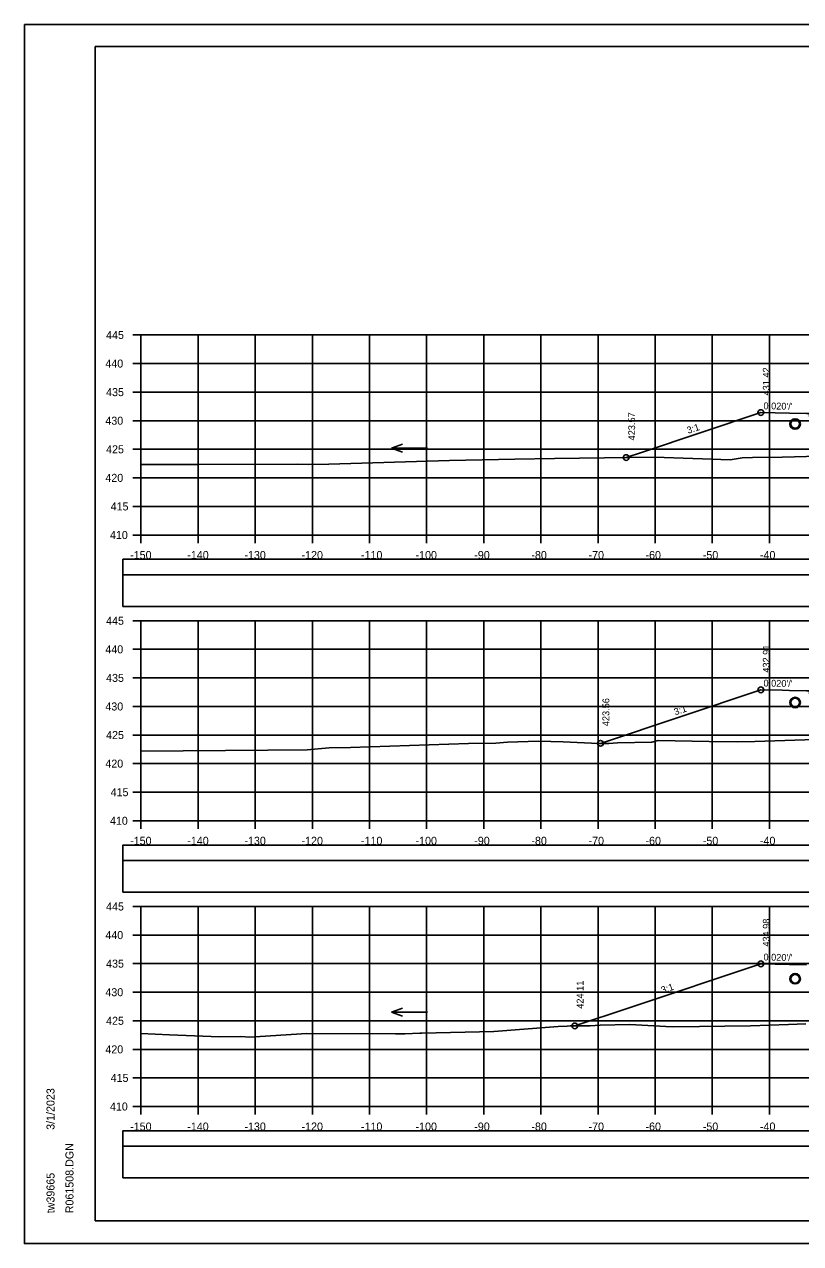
# Model space of a CAD drawing. Extents: x 1371057 to 1372761, y 380005 to 390517.
# Drawn here: x 1371390.5 to 1371526.3, y 384698.5 to 384911.8 of the extents above; entities that cross this region are included whole.
import ezdxf

# ---------------------------------------------------------------- set-up
doc = ezdxf.new("R2010")
doc.units = 0
for name, color, linetype in [('R_Axis', 7, 'Continuous'), ('R_Axis Annot', 7, 'Continuous'), ('R_Border', 7, 'Continuous'), ('R_Detour', 7, 'Continuous'), ('R_Dimension', 7, 'Continuous'), ('R_Exist Surface', 7, 'Continuous'), ('R_Fin Surface', 7, 'Continuous'), ('R_Grid', 7, 'Continuous'), ('R_No Plot', 7, 'Continuous'), ('R_Water', 7, 'Continuous'), ('R_Water Annot', 7, 'Continuous'), ('R_Xsect Elev', 7, 'Continuous'), ('R_Xsect Slope', 7, 'Continuous')]:
    doc.layers.add(name, color=color, linetype=linetype)

msp = doc.modelspace()

# ---------------------------------------------------------------- linework, layer by layer
at = {"layer": 'R_Axis'}
for p, q in [((1371409.47, 384857.5), (1371410.87, 384857.5)), ((1371410.87, 384822.5), (1371410.87, 384857.5)), ((1371409.47, 384852.5), (1371410.87, 384852.5)), ((1371409.47, 384847.5), (1371410.87, 384847.5)), ((1371409.47, 384842.5), (1371410.87, 384842.5)), ((1371409.47, 384837.5), (1371410.87, 384837.5)), ((1371409.47, 384832.5), (1371410.87, 384832.5)), ((1371409.47, 384827.5), (1371410.87, 384827.5)), ((1371409.47, 384822.5), (1371410.87, 384822.5)), ((1371410.87, 384822.5), (1371710.87, 384822.5)), ((1371410.87, 384821.1), (1371410.87, 384822.5)), ((1371420.87, 384821.1), (1371420.87, 384822.5)), ((1371430.87, 384821.1), (1371430.87, 384822.5)), ((1371440.87, 384821.1), (1371440.87, 384822.5)), ((1371450.87, 384821.1), (1371450.87, 384822.5)), ((1371460.87, 384821.1), (1371460.87, 384822.5)), ((1371470.87, 384821.1), (1371470.87, 384822.5)), ((1371480.87, 384821.1), (1371480.87, 384822.5)), ((1371490.87, 384821.1), (1371490.87, 384822.5)), ((1371500.87, 384821.1), (1371500.87, 384822.5)), ((1371510.87, 384821.1), (1371510.87, 384822.5)), ((1371520.87, 384821.1), (1371520.87, 384822.5)), ((1371409.47, 384807.5), (1371410.87, 384807.5)), ((1371410.87, 384772.5), (1371410.87, 384807.5)), ((1371409.47, 384802.5), (1371410.87, 384802.5)), ((1371409.47, 384797.5), (1371410.87, 384797.5)), ((1371409.47, 384792.5), (1371410.87, 384792.5)), ((1371409.47, 384787.5), (1371410.87, 384787.5)), ((1371409.47, 384782.5), (1371410.87, 384782.5)), ((1371409.47, 384777.5), (1371410.87, 384777.5)), ((1371409.47, 384772.5), (1371410.87, 384772.5)), ((1371410.87, 384772.5), (1371710.87, 384772.5)), ((1371410.87, 384771.1), (1371410.87, 384772.5)), ((1371420.87, 384771.1), (1371420.87, 384772.5)), ((1371430.87, 384771.1), (1371430.87, 384772.5)), ((1371440.87, 384771.1), (1371440.87, 384772.5)), ((1371450.87, 384771.1), (1371450.87, 384772.5)), ((1371460.87, 384771.1), (1371460.87, 384772.5)), ((1371470.87, 384771.1), (1371470.87, 384772.5)), ((1371480.87, 384771.1), (1371480.87, 384772.5)), ((1371490.87, 384771.1), (1371490.87, 384772.5)), ((1371500.87, 384771.1), (1371500.87, 384772.5)), ((1371510.87, 384771.1), (1371510.87, 384772.5)), ((1371520.87, 384771.1), (1371520.87, 384772.5)), ((1371409.47, 384757.5), (1371410.87, 384757.5)), ((1371410.87, 384722.5), (1371410.87, 384757.5)), ((1371409.47, 384752.5), (1371410.87, 384752.5)), ((1371409.47, 384747.5), (1371410.87, 384747.5)), ((1371409.47, 384742.5), (1371410.87, 384742.5)), ((1371409.47, 384737.5), (1371410.87, 384737.5)), ((1371409.47, 384732.5), (1371410.87, 384732.5)), ((1371409.47, 384727.5), (1371410.87, 384727.5)), ((1371409.47, 384722.5), (1371410.87, 384722.5)), ((1371410.87, 384722.5), (1371710.87, 384722.5)), ((1371410.87, 384721.1), (1371410.87, 384722.5)), ((1371420.87, 384721.1), (1371420.87, 384722.5)), ((1371430.87, 384721.1), (1371430.87, 384722.5)), ((1371440.87, 384721.1), (1371440.87, 384722.5)), ((1371450.87, 384721.1), (1371450.87, 384722.5)), ((1371460.87, 384721.1), (1371460.87, 384722.5)), ((1371470.87, 384721.1), (1371470.87, 384722.5)), ((1371480.87, 384721.1), (1371480.87, 384722.5)), ((1371490.87, 384721.1), (1371490.87, 384722.5)), ((1371500.87, 384721.1), (1371500.87, 384722.5)), ((1371510.87, 384721.1), (1371510.87, 384722.5)), ((1371520.87, 384721.1), (1371520.87, 384722.5))]:
    msp.add_line(p, q, dxfattribs=at)
at = {"layer": 'R_Border'}
for p, q in [((1371402.87, 384907.96), (1371719.05, 384907.96)), ((1371402.87, 384702.5), (1371402.87, 384907.96)), ((1371402.87, 384702.5), (1371402.87, 384702.5)), ((1371719.05, 384702.5), (1371402.87, 384702.5))]:
    msp.add_line(p, q, dxfattribs=at)
at = {"layer": 'R_Detour'}
for points in [[(1371407.72, 384815.54), (1371714.03, 384815.54), (1371714.03, 384818.25), (1371407.72, 384818.25)], [(1371407.72, 384765.54), (1371714.03, 384765.54), (1371714.03, 384768.25), (1371407.72, 384768.25)], [(1371407.72, 384715.54), (1371714.03, 384715.54), (1371714.03, 384718.25), (1371407.72, 384718.25)]]:
    msp.add_lwpolyline(points, close=True, dxfattribs=at)
at = {"layer": 'R_Dimension'}
for points in [[(1371407.72, 384810.02), (1371714.03, 384810.02), (1371714.03, 384815.54), (1371407.72, 384815.54)], [(1371407.72, 384760.02), (1371714.03, 384760.02), (1371714.03, 384765.54), (1371407.72, 384765.54)], [(1371407.72, 384710.02), (1371714.03, 384710.02), (1371714.03, 384715.54), (1371407.72, 384715.54)]]:
    msp.add_lwpolyline(points, close=True, dxfattribs=at)
at = {"layer": 'R_Exist Surface'}
for points in [[(1371410.87, 384834.84), (1371420.98, 384834.82), (1371438.32, 384834.89), (1371440.14, 384834.83), (1371443.77, 384834.92), (1371464.89, 384835.56), (1371476.28, 384835.8), (1371483.26, 384835.88), (1371500.77, 384836.13), (1371509.16, 384835.83), (1371513.98, 384835.65), (1371516.11, 384835.99), (1371517.93, 384836.08), (1371523.12, 384836.1), (1371529.53, 384836.32)], [(1371410.87, 384784.67), (1371433.09, 384784.85), (1371439.98, 384784.93), (1371443.84, 384785.25), (1371447.53, 384785.3), (1371468.18, 384786), (1371473.01, 384786.07), (1371475.04, 384786.24), (1371480.47, 384786.42), (1371484.74, 384786.29), (1371490.93, 384786.05), (1371492.79, 384786.05), (1371494.29, 384786.12), (1371500.3, 384786.23), (1371501.4, 384786.56), (1371510.32, 384786.36), (1371515.36, 384786.3), (1371518.3, 384786.39), (1371530.57, 384786.76)], [(1371410.87, 384735.27), (1371415.89, 384735.02), (1371424.63, 384734.72), (1371428.36, 384734.77), (1371429.95, 384734.65), (1371439.93, 384735.3), (1371455.4, 384735.21), (1371456.56, 384735.21), (1371457.05, 384735.24), (1371459.69, 384735.31), (1371460.02, 384735.34), (1371472.66, 384735.62), (1371483.89, 384736.48), (1371485.49, 384736.57), (1371486.02, 384736.6), (1371489.47, 384736.64), (1371491.26, 384736.71), (1371496.44, 384736.86), (1371502.75, 384736.51), (1371504.13, 384736.44), (1371517.56, 384736.62), (1371524.21, 384736.88), (1371527.27, 384736.96)]]:
    msp.add_lwpolyline(points, dxfattribs=at)
at = {"layer": 'R_Fin Surface'}
for points in [[(1371495.81, 384836.06), (1371498.63, 384837), (1371519.37, 384843.92), (1371521.88, 384843.86), (1371524.37, 384843.82), (1371527.37, 384843.76), (1371527.87, 384843.76), (1371527.87, 384843.62), (1371527.88, 384843.26), (1371528.44, 384843.27), (1371528.87, 384843.28), (1371560.87, 384843.91), (1371560.87, 384843.92), (1371560.88, 384843.91), (1371592.87, 384843.28), (1371593.87, 384843.26), (1371593.87, 384843.76), (1371594.31, 384843.76), (1371594.37, 384843.76), (1371597.37, 384843.82), (1371601.5, 384843.9), (1371602.37, 384843.92), (1371605.54, 384842.86)], [(1371491.3, 384786.05), (1371519.37, 384795.41), (1371519.37, 384795.41), (1371523.09, 384795.33), (1371524.37, 384795.31), (1371527.37, 384795.25), (1371527.87, 384795.25), (1371527.88, 384794.75), (1371528.65, 384794.76), (1371528.87, 384794.77), (1371560.87, 384795.41), (1371560.87, 384795.41), (1371592.87, 384794.77), (1371592.87, 384794.77), (1371593.5, 384794.75), (1371593.87, 384794.75), (1371593.87, 384795.25), (1371594.1, 384795.25), (1371594.37, 384795.25), (1371597.37, 384795.31), (1371599.83, 384795.36), (1371602.37, 384795.41), (1371603.72, 384794.96), (1371605.73, 384794.29)], [(1371486.79, 384736.61), (1371486.79, 384736.61), (1371486.79, 384736.61), (1371496.34, 384739.79), (1371519.37, 384747.47), (1371519.37, 384747.47), (1371524.37, 384747.37), (1371527.37, 384747.31)]]:
    msp.add_lwpolyline(points, dxfattribs=at)
at = {"layer": 'R_Grid'}
for p, q in [((1371410.87, 384857.5), (1371710.87, 384857.5)), ((1371410.87, 384822.5), (1371410.87, 384857.5)), ((1371420.87, 384822.5), (1371420.87, 384857.5)), ((1371430.87, 384822.5), (1371430.87, 384857.5)), ((1371440.87, 384822.5), (1371440.87, 384857.5)), ((1371450.87, 384822.5), (1371450.87, 384857.5)), ((1371460.87, 384822.5), (1371460.87, 384857.5)), ((1371470.87, 384822.5), (1371470.87, 384857.5)), ((1371480.87, 384822.5), (1371480.87, 384857.5)), ((1371490.87, 384822.5), (1371490.87, 384857.5)), ((1371500.87, 384822.5), (1371500.87, 384857.5)), ((1371510.87, 384822.5), (1371510.87, 384857.5)), ((1371520.87, 384822.5), (1371520.87, 384857.5)), ((1371410.87, 384852.5), (1371710.87, 384852.5)), ((1371410.87, 384847.5), (1371710.87, 384847.5)), ((1371410.87, 384842.5), (1371710.87, 384842.5)), ((1371410.87, 384837.5), (1371710.87, 384837.5)), ((1371410.87, 384832.5), (1371710.87, 384832.5)), ((1371410.87, 384827.5), (1371710.87, 384827.5)), ((1371410.87, 384822.5), (1371710.87, 384822.5)), ((1371410.87, 384807.5), (1371710.87, 384807.5)), ((1371410.87, 384772.5), (1371410.87, 384807.5)), ((1371420.87, 384772.5), (1371420.87, 384807.5)), ((1371430.87, 384772.5), (1371430.87, 384807.5)), ((1371440.87, 384772.5), (1371440.87, 384807.5)), ((1371450.87, 384772.5), (1371450.87, 384807.5)), ((1371460.87, 384772.5), (1371460.87, 384807.5)), ((1371470.87, 384772.5), (1371470.87, 384807.5)), ((1371480.87, 384772.5), (1371480.87, 384807.5)), ((1371490.87, 384772.5), (1371490.87, 384807.5)), ((1371500.87, 384772.5), (1371500.87, 384807.5)), ((1371510.87, 384772.5), (1371510.87, 384807.5)), ((1371520.87, 384772.5), (1371520.87, 384807.5)), ((1371410.87, 384802.5), (1371710.87, 384802.5)), ((1371410.87, 384797.5), (1371710.87, 384797.5)), ((1371410.87, 384792.5), (1371710.87, 384792.5)), ((1371410.87, 384787.5), (1371710.87, 384787.5)), ((1371410.87, 384782.5), (1371710.87, 384782.5)), ((1371410.87, 384777.5), (1371710.87, 384777.5)), ((1371410.87, 384772.5), (1371710.87, 384772.5)), ((1371410.87, 384757.5), (1371710.87, 384757.5)), ((1371410.87, 384722.5), (1371410.87, 384757.5)), ((1371420.87, 384722.5), (1371420.87, 384757.5)), ((1371430.87, 384722.5), (1371430.87, 384757.5)), ((1371440.87, 384722.5), (1371440.87, 384757.5)), ((1371450.87, 384722.5), (1371450.87, 384757.5)), ((1371460.87, 384722.5), (1371460.87, 384757.5)), ((1371470.87, 384722.5), (1371470.87, 384757.5)), ((1371480.87, 384722.5), (1371480.87, 384757.5)), ((1371490.87, 384722.5), (1371490.87, 384757.5)), ((1371500.87, 384722.5), (1371500.87, 384757.5)), ((1371510.87, 384722.5), (1371510.87, 384757.5)), ((1371520.87, 384722.5), (1371520.87, 384757.5)), ((1371410.87, 384752.5), (1371710.87, 384752.5)), ((1371410.87, 384747.5), (1371710.87, 384747.5)), ((1371410.87, 384742.5), (1371710.87, 384742.5)), ((1371410.87, 384737.5), (1371710.87, 384737.5)), ((1371410.87, 384732.5), (1371710.87, 384732.5)), ((1371410.87, 384727.5), (1371710.87, 384727.5)), ((1371410.87, 384722.5), (1371710.87, 384722.5))]:
    msp.add_line(p, q, dxfattribs=at)
at = {"layer": 'R_No Plot'}
for p, q in [((1371390.47, 384911.85), (1371723.8, 384911.85)), ((1371390.47, 384698.52), (1371723.8, 384698.52))]:
    msp.add_line(p, q, dxfattribs=at)
for points in [[(1371390.46, 384911.85), (1371723.8, 384911.85), (1371723.8, 384698.51), (1371390.46, 384698.51)], [(1371636.79, 384907.96), (1371656.41, 384907.96), (1371656.41, 384898.08), (1371672.52, 384898.08), (1371695.72, 384898.08), (1371695.84, 384869.92), (1371719.05, 384869.92), (1371719.05, 384702.5), (1371402.87, 384702.5), (1371402.87, 384907.96)]]:
    msp.add_lwpolyline(points, close=True, dxfattribs=at)
for centre, radius in [((1371519.37, 384843.92), 0.5), ((1371525.37, 384841.93), 0.917), ((1371495.81, 384836.06), 0.5), ((1371519.37, 384795.41), 0.5), ((1371525.37, 384793.19), 0.917), ((1371491.3, 384786.05), 0.5), ((1371519.37, 384747.47), 0.5), ((1371525.37, 384744.86), 0.917), ((1371486.79, 384736.61), 0.5)]:
    msp.add_circle(centre, radius, dxfattribs=at)
at = {"layer": 'R_Water'}
for centre in [(1371525.37, 384841.93), (1371525.37, 384793.19), (1371525.37, 384744.86)]:
    msp.add_circle(centre, 0.75, dxfattribs=at)
at = {"layer": 'R_Water Annot'}
for p, q in [((1371454.73, 384837.7), (1371456.66, 384838.4)), ((1371461.02, 384837.7), (1371454.73, 384837.7)), ((1371454.73, 384837.7), (1371456.66, 384837)), ((1371454.73, 384739.03), (1371456.66, 384739.73)), ((1371461.02, 384739.03), (1371454.73, 384739.03)), ((1371454.73, 384739.03), (1371456.66, 384738.33))]:
    msp.add_line(p, q, dxfattribs=at)

# ---------------------------------------------------------------- texts
at = {"layer": 'R_Axis Annot'}
for s, p in [('445', (1371404.77, 384856.8)), ('440', (1371404.64, 384851.8)), ('435', (1371404.77, 384846.8)), ('430', (1371404.64, 384841.8)), ('425', (1371404.77, 384836.8)), ('420', (1371404.64, 384831.8)), ('415', (1371405.56, 384826.8)), ('410', (1371405.44, 384821.8)), ('-150', (1371408.98, 384818.3)), ('-140', (1371418.98, 384818.3)), ('-130', (1371428.98, 384818.3)), ('-120', (1371438.98, 384818.3)), ('-110', (1371449.38, 384818.3)), ('-100', (1371458.93, 384818.3)), ('-90', (1371469.21, 384818.3)), ('-80', (1371479.21, 384818.3)), ('-70', (1371489.21, 384818.3)), ('-60', (1371499.18, 384818.3)), ('-50', (1371509.21, 384818.3)), ('-40', (1371519.21, 384818.3)), ('445', (1371404.77, 384806.8)), ('440', (1371404.64, 384801.8)), ('435', (1371404.77, 384796.8)), ('430', (1371404.64, 384791.8)), ('425', (1371404.77, 384786.8)), ('420', (1371404.64, 384781.8)), ('415', (1371405.56, 384776.8)), ('410', (1371405.44, 384771.8)), ('-150', (1371408.98, 384768.3)), ('-140', (1371418.98, 384768.3)), ('-130', (1371428.98, 384768.3)), ('-120', (1371438.98, 384768.3)), ('-110', (1371449.38, 384768.3)), ('-100', (1371458.93, 384768.3)), ('-90', (1371469.21, 384768.3)), ('-80', (1371479.21, 384768.3)), ('-70', (1371489.21, 384768.3)), ('-60', (1371499.18, 384768.3)), ('-50', (1371509.21, 384768.3)), ('-40', (1371519.21, 384768.3)), ('445', (1371404.77, 384756.8)), ('440', (1371404.64, 384751.8)), ('435', (1371404.77, 384746.8)), ('430', (1371404.64, 384741.8)), ('425', (1371404.77, 384736.8)), ('420', (1371404.64, 384731.8)), ('415', (1371405.56, 384726.8)), ('410', (1371405.44, 384721.8)), ('-150', (1371408.98, 384718.3)), ('-140', (1371418.98, 384718.3)), ('-130', (1371428.98, 384718.3)), ('-120', (1371438.98, 384718.3)), ('-110', (1371449.38, 384718.3)), ('-100', (1371458.93, 384718.3)), ('-90', (1371469.21, 384718.3)), ('-80', (1371479.21, 384718.3)), ('-70', (1371489.21, 384718.3)), ('-60', (1371499.18, 384718.3)), ('-50', (1371509.21, 384718.3)), ('-40', (1371519.21, 384718.3))]:
    msp.add_text(s, height=1.4, dxfattribs=at).set_placement(p)
at = {"layer": 'R_Border'}
for s, p in [('3/1/2023', (1371395.74, 384718.42)), ('R061508.DGN', (1371399.06, 384703.82)), ('tw39665', (1371395.74, 384703.82))]:
    msp.add_text(s, height=1.4, rotation=90, dxfattribs=at).set_placement(p)
at = {"layer": 'R_Xsect Elev'}
for s, p in [('431.42', (1371520.92, 384846.92)), ('423.57', (1371497.36, 384839.06)), ('432.91', (1371520.92, 384798.41)), ('423.56', (1371492.85, 384789.05)), ('434.98', (1371520.92, 384750.47)), ('424.11', (1371488.34, 384739.61))]:
    msp.add_text(s, height=1.2, rotation=90, dxfattribs=at).set_placement(p)
at = {"layer": 'R_Xsect Slope'}
for s, rotation, p in [("0.020'/'", 358.854, (1371519.82, 384844.51)), ('3:1', 18.4351, (1371506.64, 384840.2)), ("0.020'/'", 358.8539, (1371519.82, 384796)), ('3:1', 18.4359, (1371504.39, 384790.94)), ("0.020'/'", 358.8543, (1371519.82, 384748.06)), ('3:1', 18.4356, (1371502.13, 384742.25))]:
    msp.add_text(s, height=1.2, rotation=rotation, dxfattribs=at).set_placement(p)

doc.saveas('drawing.dxf')
